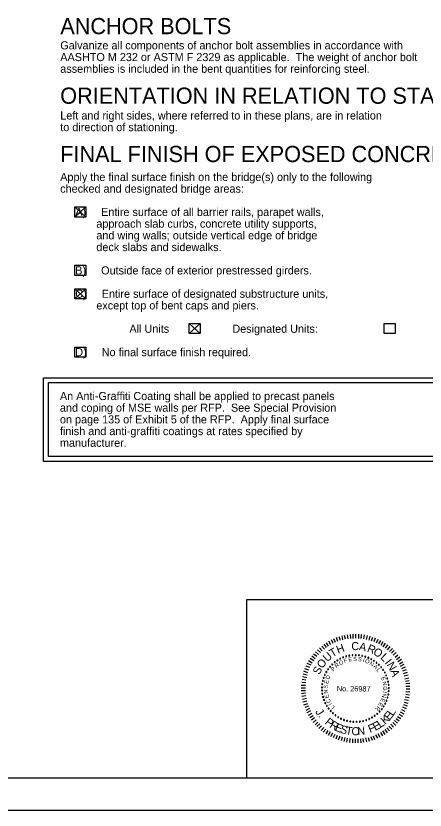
# Model space of a CAD drawing. Extents: x -1.3 to 34.8, y 0.8 to 22.8.
# Drawn here: x 17.75 to 24.06, y 0.82 to 13.07 of the extents above; entities that cross this region are included whole.
import ezdxf

# ---------------------------------------------------------------- set-up
doc = ezdxf.new("R2010")
doc.units = 0
for name, color, linetype in [('BR_BORDER LINES', 7, 'Continuous'), ('BR_TEXT', 7, 'Continuous'), ('Level 31', 7, 'Continuous')]:
    doc.layers.add(name, color=color, linetype=linetype)

msp = doc.modelspace()

# ---------------------------------------------------------------- linework, layer by layer
at = {"layer": 'BR_BORDER LINES'}
for p, q in [((21.311, 4.068), (26.676, 4.068)), ((21.311, 1.318), (21.311, 4.068)), ((0.511, 1.318), (34.177, 1.318))]:
    msp.add_line(p, q, dxfattribs=at)
at = {"layer": 'BR_TEXT'}
for p, q in [((18.654, 10.123), (18.825, 9.968)), ((18.825, 10.123), (18.654, 9.968)), ((18.826, 8.862), (18.655, 8.708)), ((18.655, 8.862), (18.826, 8.708)), ((20.419, 8.327), (20.59, 8.172)), ((20.59, 8.327), (20.419, 8.172)), ((22.641, 3.388), (22.614, 3.444)), ((22.678, 3.405), (22.654, 3.461)), ((22.716, 3.421), (22.695, 3.48)), ((22.756, 3.434), (22.734, 3.492)), ((22.792, 3.444), (22.779, 3.505)), ((22.833, 3.454), (22.819, 3.513)), ((22.873, 3.461), (22.864, 3.522)), ((22.912, 3.465), (22.909, 3.526)), ((22.952, 3.468), (22.952, 3.532)), ((22.994, 3.47), (22.994, 3.532)), ((23.036, 3.467), (23.038, 3.531)), ((23.076, 3.464), (23.081, 3.525)), ((23.115, 3.459), (23.126, 3.52)), ((23.155, 3.451), (23.169, 3.51)), ((23.196, 3.441), (23.212, 3.501)), ((23.233, 3.43), (23.255, 3.487)), ((23.272, 3.417), (23.294, 3.475)), ((23.308, 3.399), (23.336, 3.455)), ((23.344, 3.382), (23.376, 3.437)), ((22.473, 3.275), (22.431, 3.32)), ((22.506, 3.3), (22.466, 3.35)), ((22.54, 3.325), (22.501, 3.376)), ((22.571, 3.346), (22.54, 3.401)), ((22.606, 3.37), (22.576, 3.424)), ((23.382, 3.364), (23.414, 3.417)), ((23.415, 3.339), (23.449, 3.393)), ((23.448, 3.318), (23.485, 3.368)), ((23.481, 3.292), (23.522, 3.341)), ((23.512, 3.266), (23.556, 3.311)), ((22.363, 3.152), (22.314, 3.192)), ((22.389, 3.186), (22.34, 3.225)), ((22.414, 3.217), (22.371, 3.26)), ((22.444, 3.248), (22.399, 3.292)), ((23.54, 3.239), (23.584, 3.282)), ((23.569, 3.208), (23.616, 3.249)), ((23.596, 3.176), (23.642, 3.214)), ((22.3, 3.052), (22.243, 3.08)), ((22.317, 3.087), (22.263, 3.119)), ((22.341, 3.123), (22.288, 3.156)), ((23.619, 3.142), (23.669, 3.181)), ((23.641, 3.113), (23.694, 3.145)), ((23.664, 3.075), (23.717, 3.107)), ((23.681, 3.041), (23.739, 3.068)), ((22.252, 2.937), (22.191, 2.96)), ((22.265, 2.977), (22.207, 2.999)), ((22.282, 3.016), (22.225, 3.041)), ((23.699, 3.004), (23.756, 3.028)), ((23.716, 2.965), (23.773, 2.986)), ((23.729, 2.925), (23.787, 2.947)), ((22.222, 2.823), (22.161, 2.831)), ((22.233, 2.859), (22.17, 2.875)), ((22.24, 2.901), (22.179, 2.916)), ((23.739, 2.889), (23.799, 2.903)), ((23.747, 2.846), (23.808, 2.861)), ((22.215, 2.742), (22.15, 2.743)), ((22.213, 2.701), (22.15, 2.702)), ((22.218, 2.782), (22.156, 2.789)), ((23.756, 2.81), (23.815, 2.818)), ((23.762, 2.769), (23.823, 2.775)), ((23.764, 2.73), (23.824, 2.729)), ((22.214, 2.658), (22.15, 2.657)), ((22.216, 2.62), (22.154, 2.613)), ((22.22, 2.579), (22.159, 2.57)), ((23.761, 2.607), (23.822, 2.599)), ((23.763, 2.646), (23.823, 2.643)), ((23.766, 2.688), (23.827, 2.688)), ((22.23, 2.539), (22.167, 2.526)), ((22.237, 2.497), (22.176, 2.483)), ((22.248, 2.46), (22.186, 2.439)), ((23.736, 2.484), (23.796, 2.469)), ((23.745, 2.526), (23.805, 2.512)), ((23.754, 2.566), (23.813, 2.556)), ((22.26, 2.421), (22.202, 2.4)), ((22.277, 2.384), (22.219, 2.357)), ((22.294, 2.348), (22.237, 2.318)), ((23.675, 2.336), (23.733, 2.306)), ((23.694, 2.372), (23.75, 2.344)), ((23.711, 2.409), (23.768, 2.387)), ((23.725, 2.448), (23.783, 2.426)), ((22.311, 2.311), (22.256, 2.28)), ((22.334, 2.274), (22.28, 2.242)), ((22.356, 2.244), (22.306, 2.208)), ((22.381, 2.211), (22.331, 2.172)), ((23.612, 2.234), (23.661, 2.197)), ((23.634, 2.263), (23.687, 2.231)), ((23.657, 2.3), (23.71, 2.268)), ((22.406, 2.177), (22.362, 2.136)), ((22.435, 2.151), (22.39, 2.106)), ((22.464, 2.121), (22.421, 2.075)), ((22.496, 2.095), (22.455, 2.048)), ((23.471, 2.087), (23.511, 2.039)), ((23.503, 2.112), (23.545, 2.066)), ((23.531, 2.142), (23.574, 2.096)), ((23.56, 2.168), (23.607, 2.126)), ((23.588, 2.201), (23.634, 2.161)), ((22.529, 2.069), (22.489, 2.021)), ((22.56, 2.047), (22.529, 1.995)), ((22.595, 2.024), (22.564, 1.971)), ((22.629, 2.004), (22.602, 1.949)), ((22.666, 1.987), (22.641, 1.931)), ((22.704, 1.969), (22.682, 1.913)), ((23.26, 1.965), (23.281, 1.908)), ((23.297, 1.982), (23.324, 1.926)), ((23.333, 1.999), (23.363, 1.943)), ((23.371, 2.018), (23.402, 1.964)), ((23.404, 2.04), (23.437, 1.987)), ((23.438, 2.061), (23.474, 2.013)), ((22.744, 1.957), (22.721, 1.899)), ((22.78, 1.945), (22.765, 1.886)), ((22.821, 1.938), (22.806, 1.876)), ((22.86, 1.926), (22.85, 1.868)), ((22.9, 1.922), (22.895, 1.86)), ((22.939, 1.919), (22.939, 1.857)), ((22.981, 1.916), (22.981, 1.855)), ((23.023, 1.918), (23.024, 1.856)), ((23.064, 1.92), (23.067, 1.858)), ((23.102, 1.924), (23.112, 1.866)), ((23.143, 1.935), (23.156, 1.873)), ((23.184, 1.941), (23.199, 1.882)), ((23.221, 1.953), (23.242, 1.895))]:
    msp.add_line(p, q, dxfattribs=at)
for points in [[(18.654, 10.123), (18.825, 10.123), (18.825, 9.968), (18.654, 9.968)], [(18.654, 10.123), (18.825, 10.123), (18.825, 9.968), (18.654, 9.968)], [(18.655, 9.223), (18.826, 9.223), (18.826, 9.068), (18.655, 9.068)], [(18.655, 8.862), (18.826, 8.862), (18.826, 8.708), (18.655, 8.708)], [(20.419, 8.327), (20.59, 8.327), (20.59, 8.172), (20.419, 8.172)], [(23.427, 8.327), (23.598, 8.327), (23.598, 8.172), (23.427, 8.172)], [(18.655, 7.961), (18.827, 7.961), (18.827, 7.806), (18.655, 7.806)], [(18.174, 7.489), (24.535, 7.489), (24.535, 6.198), (18.174, 6.198)], [(18.248, 7.415), (24.461, 7.415), (24.461, 6.272), (18.248, 6.272)]]:
    msp.add_lwpolyline(points, close=True, dxfattribs=at)
for centre, start, end in [((22.842, 3.19), 16.1422, 196.1422), ((22.842, 3.19), 196.1422, 16.1422), ((22.89, 3.201), 10.6038, 190.6038), ((22.89, 3.201), 190.6038, 10.6038), ((22.94, 3.208), 5.0653, 185.0653), ((22.94, 3.208), 185.0653, 5.0653), ((22.99, 3.21), 359.5268, 179.5268), ((22.99, 3.21), 179.5268, 359.5268), ((23.039, 3.207), 353.9884, 173.9884), ((23.039, 3.207), 173.9884, 353.9884), ((23.089, 3.199), 348.4499, 168.4499), ((23.089, 3.199), 168.4499, 348.4499), ((23.137, 3.187), 342.9114, 162.9114), ((23.137, 3.187), 162.9114, 342.9114), ((22.628, 3.067), 43.8345, 223.8345), ((22.628, 3.067), 223.8345, 43.8345), ((22.666, 3.1), 38.2961, 218.2961), ((22.666, 3.1), 218.2961, 38.2961), ((22.706, 3.128), 32.7576, 212.7576), ((22.706, 3.128), 212.7576, 32.7576), ((22.749, 3.153), 27.2191, 207.2191), ((22.749, 3.153), 207.2191, 27.2191), ((22.795, 3.174), 21.6807, 201.6807), ((22.795, 3.174), 201.6807, 21.6807), ((23.184, 3.17), 337.373, 157.373), ((23.184, 3.17), 157.373, 337.373), ((23.229, 3.148), 151.8345, 331.8345), ((23.229, 3.148), 331.8345, 151.8345), ((23.271, 3.123), 146.2961, 326.2961), ((23.271, 3.123), 326.2961, 146.2961), ((23.311, 3.093), 140.7576, 320.7576), ((23.311, 3.093), 320.7576, 140.7576), ((23.348, 3.059), 135.2191, 315.2191), ((23.348, 3.059), 315.2191, 135.2191), ((22.536, 2.949), 60.4499, 240.4499), ((22.536, 2.949), 240.4499, 60.4499), ((22.563, 2.991), 54.9114, 234.9114), ((22.563, 2.991), 234.9114, 54.9114), ((22.594, 3.031), 49.373, 229.373), ((22.594, 3.031), 229.373, 49.373), ((23.382, 3.023), 129.6807, 309.6807), ((23.382, 3.023), 309.6807, 129.6807), ((23.412, 2.983), 124.1422, 304.1422), ((23.412, 2.983), 304.1422, 124.1422), ((23.438, 2.94), 118.6038, 298.6038), ((23.438, 2.94), 298.6038, 118.6038), ((22.496, 2.859), 71.5268, 251.5268), ((22.496, 2.859), 251.5268, 71.5268), ((22.514, 2.905), 65.9884, 245.9884), ((22.514, 2.905), 245.9884, 65.9884), ((23.459, 2.895), 113.0653, 293.0653), ((23.459, 2.895), 293.0653, 113.0653), ((23.476, 2.848), 107.5268, 287.5268), ((23.476, 2.848), 287.5268, 107.5268), ((22.469, 2.712), 88.1422, 268.1422), ((22.473, 2.762), 82.6038, 262.6038), ((22.469, 2.712), 268.1422, 88.1422), ((22.473, 2.762), 262.6038, 82.6038), ((22.482, 2.811), 77.0653, 257.0653), ((22.482, 2.811), 257.0653, 77.0653), ((23.489, 2.8), 101.9884, 281.9884), ((23.489, 2.8), 281.9884, 101.9884), ((23.497, 2.751), 96.4499, 276.4499), ((23.5, 2.701), 90.9114, 270.9114), ((23.497, 2.751), 276.4499, 96.4499), ((23.5, 2.701), 270.9114, 90.9114), ((22.47, 2.662), 93.6807, 273.6807), ((22.475, 2.613), 99.2191, 279.2191), ((22.47, 2.662), 273.6807, 93.6807), ((22.475, 2.613), 279.2191, 99.2191), ((23.492, 2.602), 79.8345, 259.8345), ((23.498, 2.652), 85.373, 265.373), ((23.492, 2.602), 259.8345, 79.8345), ((23.498, 2.652), 265.373, 85.373), ((22.485, 2.564), 104.7576, 284.7576), ((22.485, 2.564), 284.7576, 104.7576), ((22.5, 2.516), 110.2961, 290.2961), ((22.5, 2.516), 290.2961, 110.2961), ((22.52, 2.47), 115.8345, 295.8345), ((22.52, 2.47), 295.8345, 115.8345), ((23.444, 2.461), 63.2191, 243.2191), ((23.444, 2.461), 243.2191, 63.2191), ((23.465, 2.506), 68.7576, 248.7576), ((23.465, 2.506), 248.7576, 68.7576), ((23.481, 2.554), 74.2961, 254.2961), ((23.481, 2.554), 254.2961, 74.2961), ((22.544, 2.427), 121.373, 301.373), ((22.544, 2.427), 301.373, 121.373), ((22.571, 2.385), 126.9114, 306.9114), ((22.571, 2.385), 306.9114, 126.9114), ((22.603, 2.347), 132.4499, 312.4499), ((22.603, 2.347), 312.4499, 132.4499), ((23.358, 2.339), 46.6038, 226.6038), ((23.358, 2.339), 226.6038, 46.6038), ((23.391, 2.377), 52.1422, 232.1422), ((23.391, 2.377), 232.1422, 52.1422), ((23.42, 2.418), 57.6807, 237.6807), ((23.42, 2.418), 237.6807, 57.6807), ((22.638, 2.312), 137.9884, 317.9884), ((22.638, 2.312), 317.9884, 137.9884), ((22.677, 2.28), 143.5268, 323.5268), ((22.677, 2.28), 323.5268, 143.5268), ((22.718, 2.252), 149.0653, 329.0653), ((22.718, 2.252), 329.0653, 149.0653), ((22.762, 2.229), 154.6038, 334.6038), ((22.762, 2.229), 334.6038, 154.6038), ((22.808, 2.209), 160.1422, 340.1422), ((22.808, 2.209), 340.1422, 160.1422), ((23.151, 2.206), 18.9114, 198.9114), ((23.151, 2.206), 198.9114, 18.9114), ((23.197, 2.224), 24.4499, 204.4499), ((23.197, 2.224), 204.4499, 24.4499), ((23.241, 2.247), 29.9884, 209.9884), ((23.241, 2.247), 209.9884, 29.9884), ((23.283, 2.274), 35.5268, 215.5268), ((23.283, 2.274), 215.5268, 35.5268), ((23.322, 2.305), 41.0653, 221.0653), ((23.322, 2.305), 221.0653, 41.0653), ((22.856, 2.195), 345.6807, 165.6807), ((22.856, 2.195), 165.6807, 345.6807), ((22.905, 2.185), 351.2191, 171.2191), ((22.905, 2.185), 171.2191, 351.2191), ((22.954, 2.179), 356.7576, 176.7576), ((22.954, 2.179), 176.7576, 356.7576), ((23.004, 2.179), 2.2961, 182.2961), ((23.004, 2.179), 182.2961, 2.2961), ((23.054, 2.183), 7.8345, 187.8345), ((23.054, 2.183), 187.8345, 7.8345), ((23.103, 2.192), 13.373, 193.373), ((23.103, 2.192), 193.373, 13.373)]:
    msp.add_arc(centre, 0.00701, start, end, dxfattribs=at)
at = {"layer": 'Level 31'}
msp.add_lwpolyline([(-1.323, 22.818), (-1.323, 0.818), (34.677, 0.818), (34.677, 22.818)], dxfattribs=at)

# ---------------------------------------------------------------- texts
at = {"layer": 'BR_TEXT'}
for s, height, p in [('ANCHOR BOLTS', 0.25, (18.431, 12.788)), ('Galvanize all components of anchor bolt assemblies in accordance with ', 0.125, (18.431, 12.554)), ('AASHTO M 232 or ASTM F 2329 as applicable.  The weight of anchor bolt ', 0.125, (18.431, 12.373)), ('assemblies is included in the bent quantities for reinforcing steel.  ', 0.125, (18.431, 12.193)), ('ORIENTATION IN RELATION TO STATIONING', 0.25, (18.43, 11.715)), ('Left and right sides, where referred to in these plans, are in relation ', 0.125, (18.431, 11.472)), ('to direction of stationing.', 0.125, (18.431, 11.292)), ('FINAL FINISH OF EXPOSED CONCRETE SURFACES', 0.25, (18.43, 10.815)), ('Apply the final surface finish on the bridge(s) only to the following ', 0.125, (18.43, 10.523)), ('checked and designated bridge areas:', 0.125, (18.43, 10.343)), ('     A)     Entire surface of all barrier rails, parapet walls, ', 0.125, (18.43, 9.983)), ('            approach slab curbs, concrete utility supports,', 0.125, (18.43, 9.803)), ('            and wing walls; outside vertical edge of bridge', 0.125, (18.43, 9.623)), ('            deck slabs and sidewalks.', 0.125, (18.43, 9.442)), ('     B)     Outside face of exterior prestressed girders.', 0.125, (18.43, 9.082)), ('     C)     Entire surface of designated substructure units,', 0.125, (18.43, 8.722)), ('            except top of bent caps and piers.', 0.125, (18.43, 8.542)), ('                       All Units                     Designated Units:', 0.125, (18.43, 8.182)), ('     D)     No final surface finish required.  ', 0.125, (18.43, 7.821)), ('An Anti-Graffiti Coating shall be applied to precast panels ', 0.125, (18.426, 7.144)), ('and coping of MSE walls per RFP.  See Special Provision', 0.125, (18.426, 6.964)), ('on page 135 of Exhibit 5 of the RFP.  Apply final surface', 0.125, (18.426, 6.784)), ('finish and anti-graffiti coatings at rates specified by ', 0.125, (18.426, 6.603)), ('manufacturer.', 0.125, (18.426, 6.423))]:
    msp.add_text(s, height=height, dxfattribs=at).set_placement(p)
for s, height, rotation, p in [('T', 0.124, 30.4992, (22.629, 3.172)), ('H', 0.124, 20.3637, (22.717, 3.229)), ('C', 0.124, 359.5482, (22.921, 3.287)), ('A', 0.124, 348.1981, (23.033, 3.288)), ('R', 0.124, 337.4344, (23.156, 3.268)), ('O', 0.124, 326.5869, (23.248, 3.232)), ('U', 0.124, 40.8022, (22.548, 3.097)), ('L', 0.124, 315.9488, (23.361, 3.164)), ('O', 0.124, 52.0267, (22.473, 2.993)), ('R', 0.0622, 40.3949, (22.695, 3.006)), ('O', 0.0622, 30.8477, (22.751, 3.05)), ('F', 0.0622, 20.6127, (22.818, 3.086)), ('E', 0.0622, 11.4103, (22.883, 3.108)), ('S', 0.0622, 2.208, (22.951, 3.119)), ('S', 0.0622, 352.6608, (23.022, 3.119)), ('I', 0.0622, 343.1136, (23.093, 3.107)), ('O', 0.0622, 338.4392, (23.126, 3.097)), ('N', 0.0622, 328.2042, (23.196, 3.065)), ('I', 0.124, 308.6613, (23.432, 3.09)), ('N', 0.124, 300.7037, (23.463, 3.06)), ('S', 0.124, 63.2511, (22.428, 2.897)), ('P', 0.0622, 49.9421, (22.646, 2.954)), ('A', 0.0622, 318.657, (23.255, 3.025)), ('L', 0.0622, 309.4546, (23.304, 2.978)), ('A', 0.124, 289.4792, (23.522, 2.967)), ('E', 0.0622, 78.2388, (22.563, 2.762)), ('D', 0.0622, 69.0364, (22.579, 2.828)), ('E', 0.0622, 291.049, (23.378, 2.862)), ('S', 0.0622, 87.786, (22.557, 2.691)), ('No. 26987', 0.0817, 359.5268, (22.698, 2.652)), ('N', 0.0622, 281.8466, (23.4, 2.797)), ('G', 0.0622, 272.2995, (23.412, 2.727)), ('N', 0.0622, 97.3332, (22.563, 2.62)), ('E', 0.0622, 106.5355, (22.58, 2.553)), ('N', 0.0622, 257.7339, (23.407, 2.619)), ('I', 0.0622, 262.4084, (23.412, 2.653)), ('C', 0.0622, 116.4266, (22.61, 2.486)), ('I', 0.0622, 121.1011, (22.628, 2.456)), ('E', 0.0622, 238.9844, (23.361, 2.487)), ('E', 0.0622, 248.1867, (23.389, 2.55)), ('J', 0.124, 302.9559, (22.361, 2.335)), ('L', 0.0622, 129.9595, (22.669, 2.404)), ('R', 0.0622, 229.782, (23.324, 2.43)), ('E', 0.124, 49.3639, (23.507, 2.193)), ('L', 0.124, 56.4247, (23.565, 2.261)), ('.', 0.124, 309.3974, (22.405, 2.267)), ('P', 0.124, 321.1035, (22.504, 2.158)), ('K', 0.124, 42.3031, (23.442, 2.133)), ('R', 0.124, 328.5359, (22.577, 2.1)), ('E', 0.124, 335.9684, (22.657, 2.052)), ('S', 0.124, 343.0292, (22.738, 2.016)), ('T', 0.124, 350.4617, (22.828, 1.99)), ('O', 0.124, 358.1419, (22.923, 1.975)), ('N', 0.124, 5.8221, (23.02, 1.973)), ('F', 0.124, 21.1206, (23.209, 2.007)), ('E', 0.124, 28.1814, (23.291, 2.039)), ('L', 0.124, 35.2422, (23.369, 2.082))]:
    msp.add_text(s, height=height, rotation=rotation, dxfattribs=at).set_placement(p)

doc.saveas('drawing.dxf')
